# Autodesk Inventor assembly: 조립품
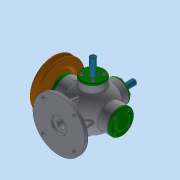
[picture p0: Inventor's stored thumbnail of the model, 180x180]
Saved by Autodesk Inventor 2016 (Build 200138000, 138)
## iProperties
Created: 2019-11
Part Number: 조립품
Material: 일반
Document SubType Name: Assembly
Designer: user
Author: user
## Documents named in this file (17)
- C:\Users\user\Desktop\391120V1008\조립품.iam
- C:\Users\user\Desktop\391120V1008\V-벨트풀리.ipt
- C:\Users\user\Desktop\391120V1008\너트 M8x1.ipt
- C:\Users\user\Desktop\391120V1008\뒤커버.ipt
- C:\Users\user\Desktop\391120V1008\베어링 6202.ipt
- C:\Users\user\Desktop\391120V1008\본체.ipt
- C:\Users\user\Desktop\391120V1008\본체커버.ipt
- C:\Users\user\Desktop\391120V1008\볼트 M4.ipt
- C:\Users\user\Desktop\391120V1008\스프링1.ipt
- C:\Users\user\Desktop\391120V1008\스프링2.ipt
- C:\Users\user\Desktop\391120V1008\슬라이드 커버.ipt
- C:\Users\user\Desktop\391120V1008\슬라이드.ipt
- C:\Users\user\Desktop\391120V1008\앞커버.ipt
- C:\Users\user\Desktop\391120V1008\오일 실.ipt
- C:\Users\user\Desktop\391120V1008\와셔 8x17.ipt
- C:\Users\user\Desktop\391120V1008\축.ipt
- C:\Users\user\Desktop\391120V1008\키 4x4.ipt
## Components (1 placed, 1 different names)
1. V-벨트풀리:1
